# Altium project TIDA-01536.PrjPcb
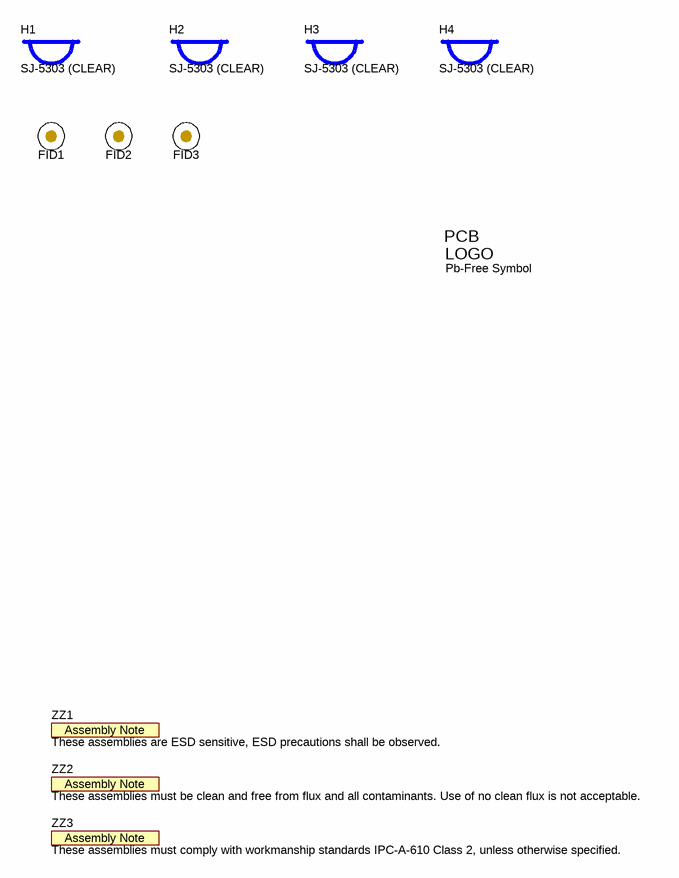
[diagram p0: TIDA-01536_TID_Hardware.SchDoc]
CopyrightYear: 2017; EVM_Orderable: N/A; PCB_Layout: CW; PCB_Rev: A; PRJ_Customer: Public Release; PRJ_Engineer: CW + KD; PRJ_Number: TIDA-01536; PRJ_Title: Single-Channel, Isolated, 3-Wire Current Loop Transmitter Reference Design; SCH_Rev: A; TechSupport: http://www.ti.com/support; TID: TIDA-01536
3 sheets, 52 parts. Net scope: global (net labels, ports and power ports of the same name join across sheets).
Board file: TIDA-01536_TID.PcbDoc
Sheets:
  TIDA-01536_TID_Hardware.SchDoc
  TIDA-01536_CoverSheet.SchDoc
  TIDA-01536_BlankSheet.SchDoc

## Sheet TIDA-01536_TID_Hardware.SchDoc
size 431 x 279 mm; Date: Not shown in title block; ApprovedBy: Not shown in title block; CheckedBy: Not shown in title block; Author: Not shown in title block; CompanyName: Not shown in title block; Engineer: Not shown in title block; Organization: Not shown in title block; Address1: Not shown in title block; Address2: Not shown in title block; Address3: Not shown in title block; Address4: Not shown in title block; DocumentNumber: 1; Revision: Use project parameter SCH_Rev; SheetNumber: 3; SheetTotal: 3; PageSetup: Record=PageOptions¦CenterHorizontal=True¦CenterVertical=True¦PrintScale=1.00¦XCorrection=1.00¦YCorrection=1.00¦PrintKind=0¦BorderSize=5000000¦LeftOffset=0¦BottomOffset=0¦Orientation=2¦PaperLength=1000¦PaperWidth=1000¦Scale=100¦PaperSource=15¦PrintQuality=600¦MediaType=1¦DitherType=10¦PaperKind=Letter¦PrintScaleMode=1

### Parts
FID1  Fiducial  [Fiducial10-20]  (value not drawn)
FID2  Fiducial  [Fiducial10-20]  (value not drawn)
FID3  Fiducial  [Fiducial10-20]  (value not drawn)
H1  SJ-5303 (CLEAR)  [Bumpon_SJ5003Transparent]
H2  SJ-5303 (CLEAR)  [Bumpon_SJ5003Transparent]
H3  SJ-5303 (CLEAR)  [Bumpon_SJ5003Transparent]
H4  SJ-5303 (CLEAR)  [Bumpon_SJ5003Transparent]
Logo2  Pb-Free Symbol  [Pb-Free_Overlay_Small]  (no BOM)
ZZ1  These assemblies are ESD sensitive, ESD precautions shall be observed.  [AssemblyNote]  (no BOM)
ZZ2  These assemblies must be clean and free from flux and all contaminants. Use of no clean flux is not acceptable.  [AssemblyNote]  (no BOM)
ZZ3  These assemblies must comply with workmanship standards IPC-A-610 Class 2, unless otherwise specified.  [AssemblyNote]  (no BOM)

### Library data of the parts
FID1-FID3 = Fiducial: Fiducial mark.  There is nothing to buy or mount.; SymbolCreator: codlsc
H1-H4 = SJ-5303 (CLEAR): Bumpon, Hemisphere, 0.44 X 0.20, Clear; Manufacturer: 3M; SymbolCreator: a0412235
Logo2 = Pb-Free: SymbolCreator: a0412235
ZZ1-ZZ3 = AssemblyNote: SymbolCreator: codlsc

## Sheet TIDA-01536_CoverSheet.SchDoc
size 431 x 279 mm; Date: Not shown in title block; ApprovedBy: Not shown in title block; CheckedBy: Not shown in title block; Author: Not shown in title block; CompanyName: Not shown in title block; Engineer: Not shown in title block; Organization: Not shown in title block; Address1: Not shown in title block; Address2: Not shown in title block; Address3: Not shown in title block; Address4: Not shown in title block; DocumentNumber: 1; Revision: Use project parameter SCH_Rev; SheetNumber: 1; SheetTotal: 3; PageSetup: Record=PageOptions¦CenterHorizontal=True¦CenterVertical=True¦PrintScale=1.00¦XCorrection=1.00¦YCorrection=1.00¦PrintKind=0¦BorderSize=5000000¦LeftOffset=0¦BottomOffset=0¦Orientation=2¦PaperLength=1000¦PaperWidth=1000¦Scale=100¦PaperSource=15¦PrintQuality=600¦MediaType=1¦DitherType=10¦PaperKind=Letter¦PrintScaleMode=1
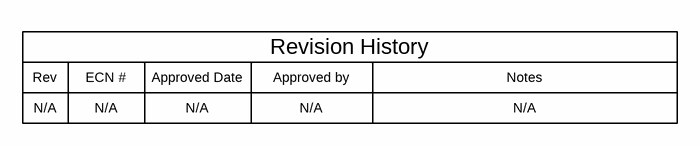
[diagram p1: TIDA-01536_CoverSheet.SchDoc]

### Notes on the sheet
- Rev
- N/A
- ECN #
- Approved Date
- Approved by
- Revision History
- Notes

## Sheet TIDA-01536_BlankSheet.SchDoc
size 431 x 279 mm; Date: Not shown in title block; ApprovedBy: Not shown in title block; CheckedBy: Not shown in title block; Author: Not shown in title block; CompanyName: Not shown in title block; DrawnBy: CW; Engineer: Not shown in title block; Organization: Not shown in title block; Address1: Not shown in title block; Address2: Not shown in title block; Address3: Not shown in title block; Address4: Not shown in title block; DocumentNumber: TIPD203; Revision: Use project parameter SCH_Rev; SheetNumber: 2; SheetTotal: 3; PageSetup: Record=PageOptions¦CenterHorizontal=True¦CenterVertical=True¦PrintScale=1.00¦XCorrection=1.00¦YCorrection=1.00¦PrintKind=0¦BorderSize=5000000¦LeftOffset=0¦BottomOffset=0¦Orientation=2¦PaperLength=1000¦PaperWidth=1000¦Scale=100¦PaperSource=15¦PrintQuality=600¦MediaType=1¦DitherType=10¦PaperKind=Letter¦PrintScaleMode=1
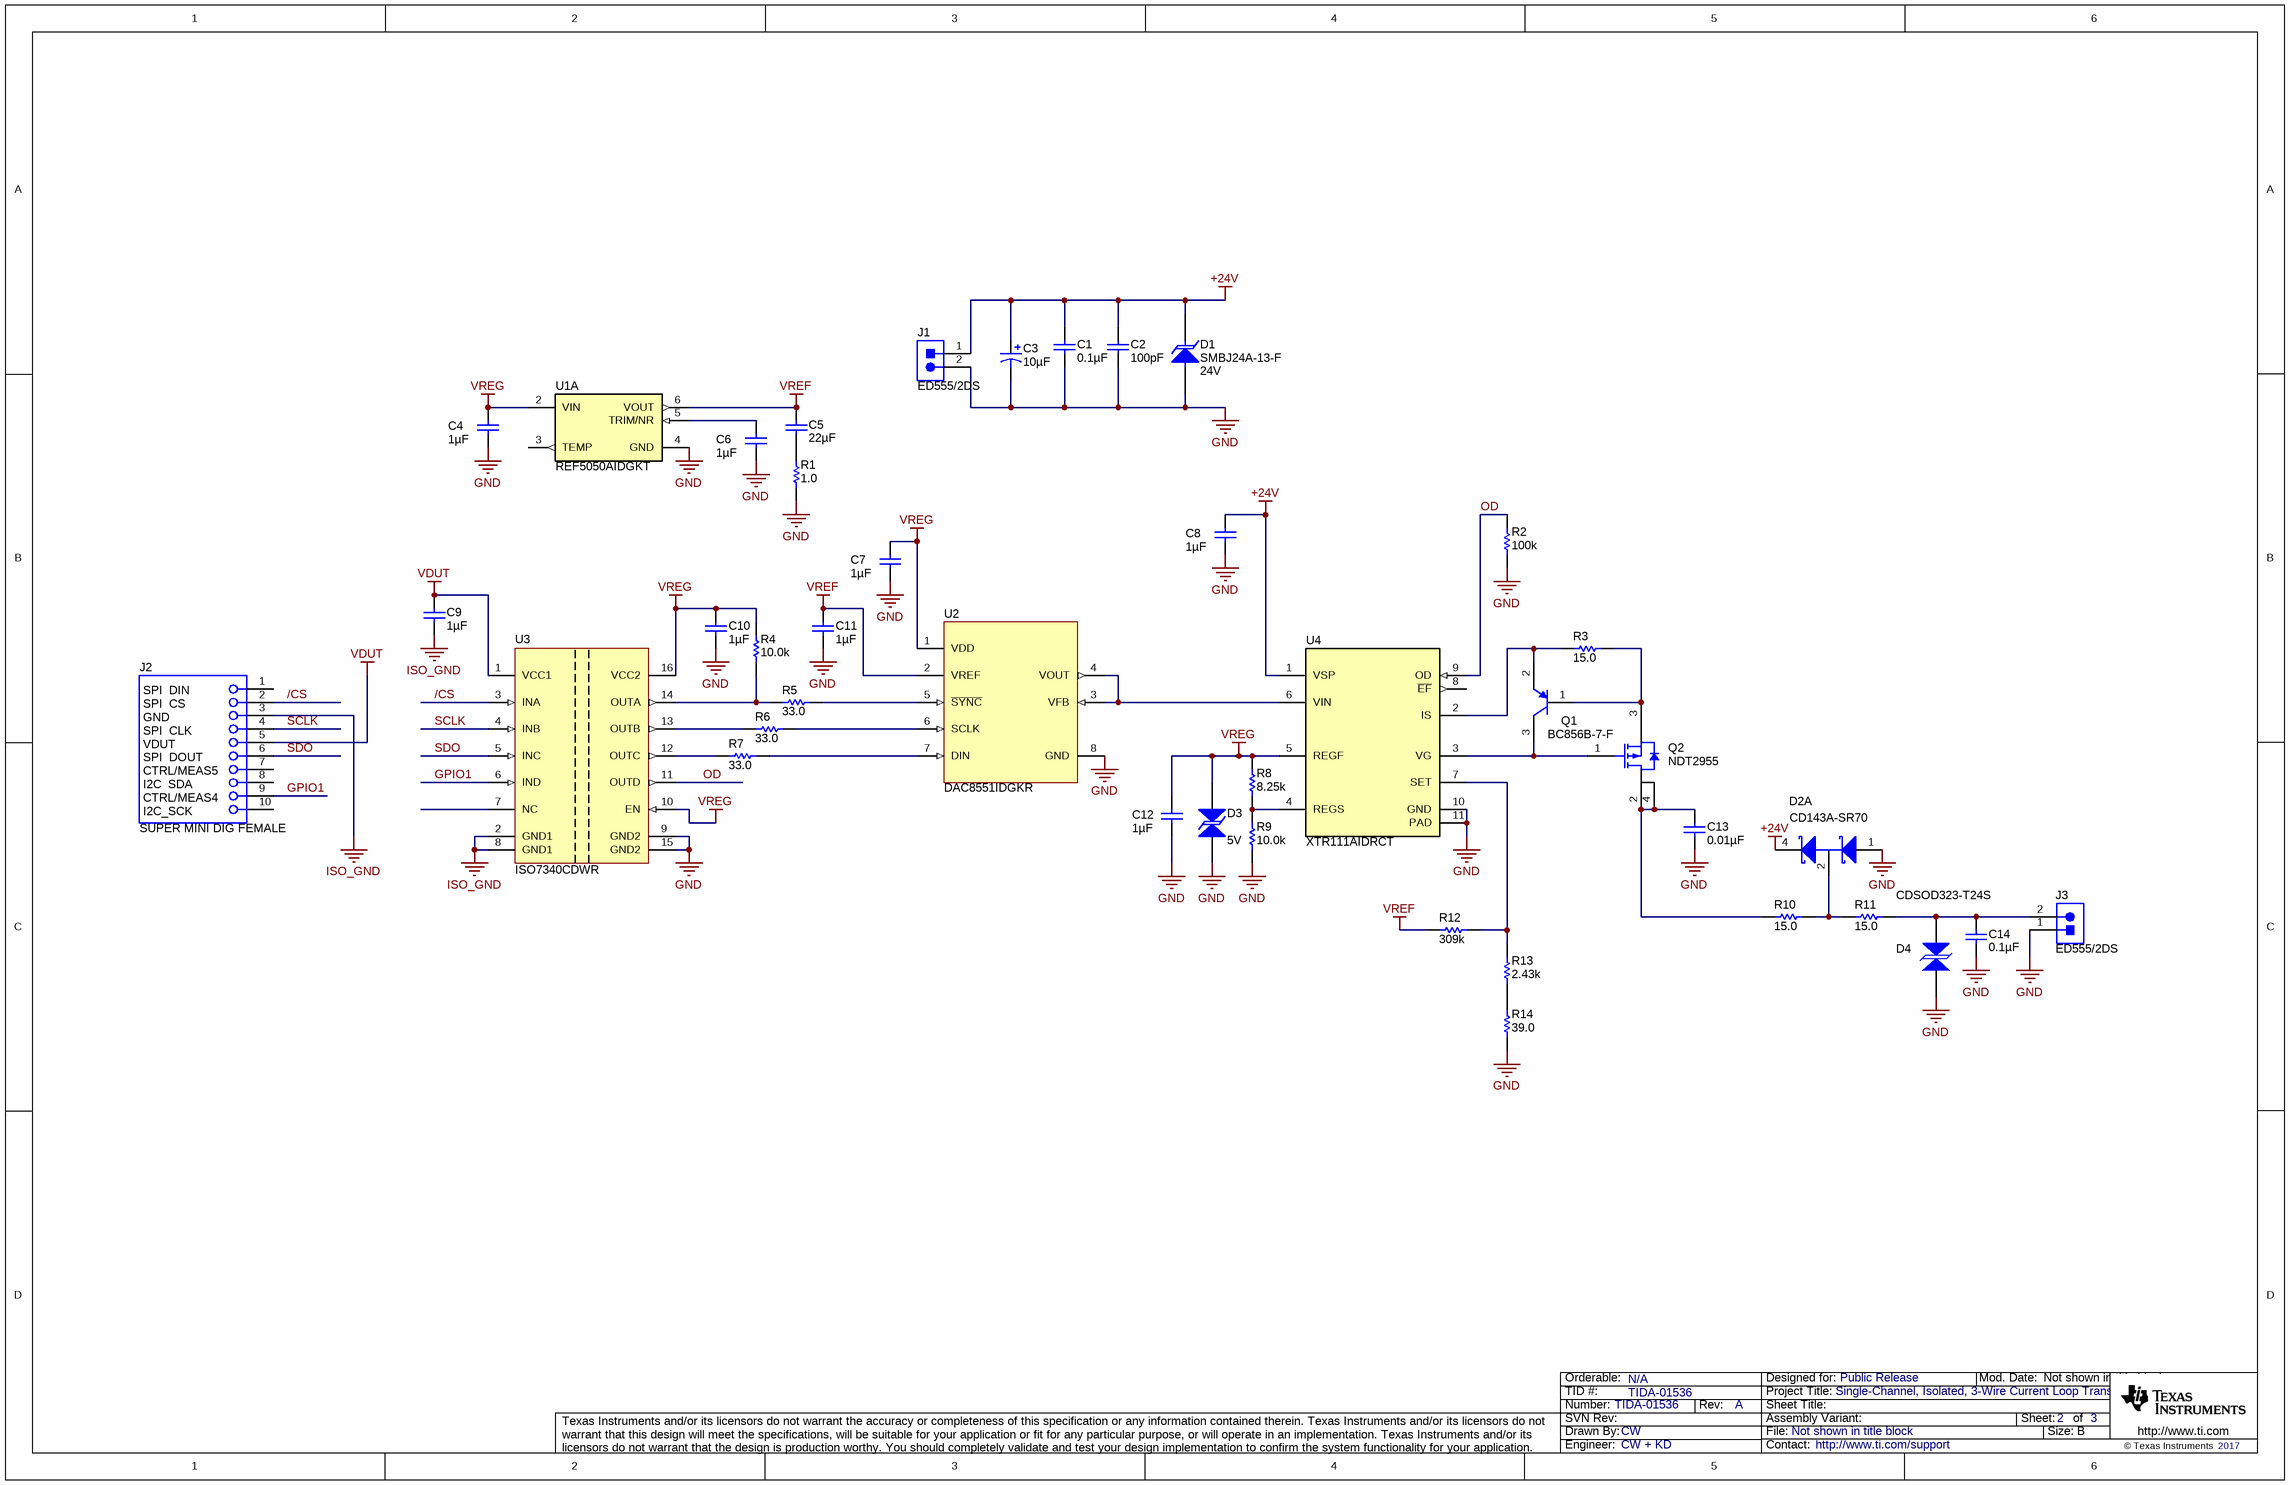
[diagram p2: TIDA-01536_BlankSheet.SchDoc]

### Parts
C1  ValueDisplayed: 0.1µF  [0603]  (hidden comment: GRM188R71H104KA93D)
C2  ValueDisplayed: 100pF  [0603]  (hidden comment: 06035A101JAT2A)
C3  ValueDisplayed: 10µF  [7343-43]  (hidden comment: 293D106X9050E2TE3)
C4  ValueDisplayed: 1µF  [0603]  (hidden comment: GRM188R71E105KA12D)
C5  ValueDisplayed: 22µF  [1206]  (hidden comment: GRM31CR61C226ME15L)
C6  ValueDisplayed: 1µF  [0603]  (hidden comment: GRM188R71E105KA12D)
C7  ValueDisplayed: 1µF  [0603]  (hidden comment: GRM188R71E105KA12D)
C8  ValueDisplayed: 1µF  [0603]  (hidden comment: GRM188R71E105KA12D)
C9  ValueDisplayed: 1µF  [0603]  (hidden comment: GRM188R71E105KA12D)
C10  ValueDisplayed: 1µF  [0603]  (hidden comment: GRM188R71E105KA12D)
C11  ValueDisplayed: 1µF  [0603]  (hidden comment: GRM188R71E105KA12D)
C12  ValueDisplayed: 1µF  [0603]  (hidden comment: GRM188R71E105KA12D)
C13  ValueDisplayed: 0.01µF  [0603]  (hidden comment: GRM188R72A103KA01D)
C14  ValueDisplayed: 0.1µF  [0603]  (hidden comment: GRM188R71H104KA93D)
D1  SMBJ24A-13-F  value 24V  [SMB]
D2  CD143A-SR70  [SOT-143-4]  (part A of 2)
D3  value 5V  [SOD-323-Bi]  (hidden comment: CDSOD323-T05)
D4  CDSOD323-T24S  [sod-323]
J1  ED555/2DS  [TERM_BLK_ED555-2DS]
J2  SUPER MINI DIG FEMALE  [CONN_851-43-010-20-001000]
J3  ED555/2DS  [TERM_BLK_ED555-2DS]
Q1  BC856B-7-F  [SOT-23]
Q2  NDT2955  [SOT-223]
R1  ValueDisplayed: 1.0  [0603]  (hidden comment: CRCW06031R00JNEA)
R2  ValueDisplayed: 100k  [0603]  (hidden comment: CRCW0603100KFKEA)
R3  ValueDisplayed: 15.0  [0603]  (hidden comment: CRCW060315R0FKEA)
R4  ValueDisplayed: 10.0k  [0603]  (hidden comment: RC0603FR-0710KL)
R5  ValueDisplayed: 33.0  [0603]  (hidden comment: CRCW060333R0FKEA)
R6  ValueDisplayed: 33.0  [0603]  (hidden comment: CRCW060333R0FKEA)
R7  ValueDisplayed: 33.0  [0603]  (hidden comment: CRCW060333R0FKEA)
R8  ValueDisplayed: 8.25k  [0603]  (hidden comment: RG1608P-8251-B-T5)
R9  ValueDisplayed: 10.0k  [0603]  (hidden comment: RG1608P-103-B-T5)
R10  ValueDisplayed: 15.0  [0805_HV]  (hidden comment: CRCW080515R0FKEA)
R11  ValueDisplayed: 15.0  [0805_HV]  (hidden comment: CRCW080515R0FKEA)
R12  ValueDisplayed: 309k  [0603]  (hidden comment: RG1608P-3093-B-T5)
R13  ValueDisplayed: 2.43k  [0603]  (hidden comment: RG1608P-2431-B-T5)
R14  ValueDisplayed: 39.0  [0603]  (hidden comment: 2-1676481-2)
U1  REF5050AIDGKT  [DGK0008A_N]  (part A of 2)
U2  DAC8551IDGKR  [DGK0008A_N]
U3  ISO7340CDWR  [DW0016B_N]
U4  XTR111AIDRCT  [DRC0010A]

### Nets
+24V: C1.2 C2.1 C3.1(+) C8.1 D1.1(K) D2.4 J1.1 U4.1(VSP)
GND: C1.1 C2.2 C3.2(-) C4.2 C6.2 C7.2 C8.2 C10.2 C11.2 C12.2 C13.2 C14.2 D1.2(A) D2.1 D3.1 D4.2 J1.2 J3.1 R1.1 R2.1 R9.2 R14.1 U1.4(GND) U2.8(GND) U3.9(GND2) U3.15(GND2) U4.10(GND) U4.11(PAD)
ISO_GND: C9.2 J2.3 U3.2(GND1) U3.8(GND1)
VDUT: C9.1 J2.5 U3.1(VCC1)
VREF: C5.1 C11.1 R12.2 U1.6(VOUT) U2.2(VREF)
VREG: C4.1 C7.1 C10.1 C12.1 D3.2 R4.2 R8.1 U1.2(VIN) U2.1(VDD) U3.10(EN) U3.16(VCC2) U4.5(REGF)
/CS: J2.2 U3.3(INA)
GPIO1: J2.9 U3.6(IND)
OD: R2.2 U3.11(OUTD) U4.9(OD)
SCLK: J2.4 U3.4(INB)
SDO: J2.6 U3.5(INC)
NetC5_2: C5.2 R1.2
NetC6_1: C6.1 U1.5(TRIM/NR)
NetC13_1: C13.1 Q2.2(D) Q2.4(D) R10.1
NetC14_1: C14.1 D4.1 J3.2 R11.2
NetD2_2: D2.2 R10.2 R11.1
NetQ1_1: Q1.1(B) Q2.3(S) R3.2
NetQ1_2: Q1.2(E) R3.1 U4.2(IS)
NetQ1_3: Q1.3(C) Q2.1(G) U4.3(VG)
NetR4_1: R4.1 R5.1 U3.14(OUTA)
NetR5_2: R5.2 U2.5(~{SYNC})
NetR6_1: R6.1 U3.13(OUTB)
NetR6_2: R6.2 U2.6(SCLK)
NetR7_1: R7.1 U3.12(OUTC)
NetR7_2: R7.2 U2.7(DIN)
NetR8_2: R8.2 R9.1 U4.4(REGS)
NetR12_1: R12.1 R13.2 U4.7(SET)
NetR13_1: R13.1 R14.2
NetU2_3: U2.3(VFB) U2.4(VOUT) U4.6(VIN)

Not connected (* = marked no-connect by the designer): J2 1 7 8 10; U1 3(TEMP); U3 7(NC); U4 8(~{EF})

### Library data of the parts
C1 C14 = GRM188R71H104KA93D: CAP, CERM, 0.1uF, 50V, +/-10%, X7R, 0603; Manufacturer: MuRata; Polarized: N; CompType: Capacitor; U/M: EA; Cap_F: 0.0000001; Tolerance_%: 10; VDC_V: 50; TaMin_C: -55; TaMax_C: 125
C2 = 06035A101JAT2A: CAP, CERM, 100pF, 50V, +/-5%, C0G/NP0, 0603; Manufacturer: AVX; Polarized: N; CompType: Capacitor; U/M: EA; Cap_F: 0.0000000001; Tolerance_%: 5; ESR_Ohm: 0.119; Value1: 0.119 ohm; VDC_V: 50; TaMin_C: -55; TaMax_C: 125
C3 = 293D106X9050E2TE3: CAP, TANT, 10uF, 50V, +/-10%, 0.8 ohm, 7343-43 SMD; Manufacturer: Vishay-Sprague; Polarized: Y; CompType: Capacitor; U/M: EA; Cap_F: 0.00001; Tolerance_%: 10; Value1: 0.8 ohm; VDC_V: 50; ESR_Ohm: 0.8; IRMS_A: 0.45; TaMin_C: -55; TaMax_C: 125; Cap_Case: E
C4 C6-C12 = GRM188R71E105KA12D: CAP, CERM, 1 µF, 25 V, +/- 10%, X7R, 0603; Manufacturer: MuRata; Polarized: N; CompType: Capacitor; Value: 1uF; U/M: EA; Cap_F: 0.000001; Tolerance_%: 10; Value1: Unknown; VDC_V: 25; Value2: 25V; TaMin_C: -55; TaMax_C: 125; AEC Category: Q200
C5 = GRM31CR61C226ME15L: CAP, CERM, 22 µF, 16 V, +/- 20%, X5R, 1206; Manufacturer: MuRata; Polarized: N; CompType: Capacitor; Value: 22uF; U/M: EA; Cap_F: 0.000022; Tolerance_%: 20; ESR_ohm: 0.006; Value1: 0.006 ohm; VDC_V: 16; Value2: 16V; TaMin_C: -55; TaMax_C: 85; AEC Category: Q200
C13 = GRM188R72A103KA01D: CAP, CERM, 0.01 µF, 100 V, +/- 10%, X7R, 0603; Manufacturer: MuRata; Polarized: N; CompType: Capacitor; Value: 0.01uF; U/M: EA; Cap_F: 0.00000001; Tolerance_%: 10; Value1: Unknown; VDC_V: 100; Value2: 100V; TaMin_C: -55; TaMax_C: 125; AEC Category: Q200
D1 = SMBJ24A-13-F: Diode, TVS, Uni, 24 V, 600 W, SMB; Manufacturer: Diodes Inc.; U/M: EA; Power_W: 5; Vr_V: 24; Value1: 5W; AEC Category: Q101
D2 = CD143A-SR70: IC TVS ARRAY 2-LINE 70V SOT-143; Manufacturer: Bourns; SymbolVersion: use current date i.e. 2008-05-20; SymbolCreator: Use LDAP id; U/M: EA, IN, or GM
D3 = CDSOD323-T05C: TVS DIODE 5VWM 9.8VC SOD323; Manufacturer: Bourns; U/M: EA; Power_W: 350; Vr_V: 5; Value1: 350W; AEC Category: Q101
D4 = SMAJ15CA: TVS DIODE 24VWM 43VC SMD; Manufacturer: Bourns; SymbolVersion: use current date i.e. 2008-05-20; SymbolCreator: Use LDAP id; U/M: EA, IN, or GM
J1 J3 = ED555/2DS: Terminal Block, 6A, 3.5mm Pitch, 2-Pos, TH; Manufacturer: On-Shore Technology; SymbolCreator: a0412235; CompType: Connector; U/M: EA
J2 = 851-43-010-20-001000: Receptacle, 50mil 10x1, R/A, TH; Manufacturer: Mill-Max; SymbolCreator: a0411947; U/M: EA
Q1 = BC856B-7-F, Diodes Inc.: Transistor, PNP, 65 V, 0.1 A, SOT-23; CompType: BJT; PNP: 1; NPN: 0; Vceo_V: 65; Vcesat1_V: 0.075; Value: 65 V; IcRated_A: 0.1; Value1: 0.1 A; HfeMax: 330; TaMin_C: -65; TaMax_C: 150; U/M: EA; AEC Category: Q101
Q2 = NDT2955: MOSFET, P-CH, -60 V, -2.5 A, SOT-223; Manufacturer: Fairchild Semiconductor; Alternate Manufacturer: None; SymbolCreator: a0799628; U/M: EA; ChType: P; Value: -60V; Value1: 0.5 ohm; Rdson45_ohm: 0.5; Value2: 11 nC; QgTyp_nC: 11; Vgs_V: 20; AEC Category: Q101
R1 = CRCW06031R00JNEA: RES, 1.0, 5%, 0.1 W, 0603; Manufacturer: Vishay-Dale; CompType: Resistor; Value: 1.0; Res_ohm: 1; Value_Code: 1R00; Tolerance_%: 5; Power_W: 0.1; Value2: 0.1W; VDC_V: 75; TempCo: 200 ppm/C; EIA_Code: E24; U/M: EA; AEC Category: Q200
R2 = CRCW0603100KFKEA: RES, 100 k, 1%, 0.1 W, 0603; Manufacturer: Vishay-Dale; CompType: Resistor; Value: 100k; Res_ohm: 100000; Tolerance_%: 1; Power_W: 0.1; Value2: 0.1W; VDC_V: 75; TempCo: 100 ppm/C; EIA_Code: E96; U/M: EA; AEC Category: Q200
R3 = CRCW060315R0FKEA: RES, 15.0, 1%, 0.1 W, 0603; Manufacturer: Vishay-Dale; CompType: Resistor; Value: 15.0; Res_ohm: 15; Value_Code: 15R0; Tolerance_%: 1; Power_W: 0.1; Value2: 0.1W; VDC_V: 75; TempCo: 100 ppm/C; EIA_Code: E96; U/M: EA; AEC Category: Q200
R4 = RC0603FR-0710KL: RES, 10.0 k, 1%, 0.1 W, 0603; Manufacturer: Yageo America; CompType: Resistor; Value: 10.0k; Res_ohm: 10000; Value_Code: 10k0; Tolerance_%: 1; Power_W: 0.1; Value2: 0.1W; VDC_V: 150; TempCo: 200 ppm/C; EIA_Code: E96; U/M: EA; AEC Category: Q200
R5-R7 = CRCW060333R0FKEA: RES, 33.0, 1%, 0.1 W, 0603; Manufacturer: Vishay-Dale; CompType: Resistor; Value: 33.0; Res_ohm: 33; Value_Code: 33R0; Tolerance_%: 1; Power_W: 0.1; Value2: 0.1W; VDC_V: 75; TempCo: 100 ppm/C; U/M: EA; AEC Category: Q200
R8 = RG1608P-8251-B-T5: RES, 8.25 k, 0.1%, 0.1 W, 0603; Manufacturer: Susumu Co Ltd; CompType: Resistor; Value: 8.25k; Res_ohm: 8250; Value_Code: 8k25; Tolerance_%: 0.1; Value2: 0.1W; VDC_V: 75; TempCo: 25 ppm/C; EIA_Code: E192; U/M: EA; AEC Category: Q200
R9 = RG1608P-103-B-T5: RES, 10.0 k, 0.1%, 0.1 W, 0603; Manufacturer: Susumu Co Ltd; CompType: Resistor; Value: 10.0k; Res_ohm: 10000; Value_Code: 10k0; Tolerance_%: 0.1; Value2: 0.1W; VDC_V: 75; TempCo: 25 ppm/C; EIA_Code: E192; U/M: EA; AEC Category: Q200
R10 R11 = CRCW080515R0FKEA: RES, 15.0, 1%, 0.125 W, 0805; Manufacturer: Vishay-Dale; CompType: Resistor; Value: 15.0; Res_ohm: 15; Value_Code: 15R0; Tolerance_%: 1; Power_W: 0.125; Value2: 0.125W; VDC_V: 150; TempCo: 100 ppm/C; EIA_Code: E96; U/M: EA; AEC Category: Q200
R12 = RG1608P-3093-B-T5: RES, 309 k, 0.1%, 0.1 W, 0603; Manufacturer: Susumu Co Ltd; CompType: Resistor; Value: 309k; Res_ohm: 309000; Tolerance_%: 0.1; Value2: 0.1W; VDC_V: 75; TempCo: 25 ppm/C; EIA_Code: E192; U/M: EA; AEC Category: Q200
R13 = RG1608P-2431-B-T5: RES, 2.43 k, 0.1%, 0.1 W, 0603; Manufacturer: Susumu Co Ltd; CompType: Resistor; Value: 2.43k; Res_ohm: 2430; Value_Code: 2k43; Tolerance_%: 0.1; Value2: 0.1W; VDC_V: 75; TempCo: 25 ppm/C; EIA_Code: E192; U/M: EA; AEC Category: Q200
R14 = RC0603FR-0739RL: RES SMD 39 OHM 0.1% 1/16W 0603; Manufacturer: TE Connectivity; CompType: Resistor; Value: 39.0; Res_ohm: 39; Value_Code: 39R0; Tolerance_%: 1; Power_W: 0.1; Value2: 0.1W; VDC_V: 150; U/M: EA; AEC Category: Q200
U1 = REF5050AIDGKT: Low Noise, Very Low Drift, Precision Voltage Reference, -40 to 125 degC, 8-pin VSSOP (DGK), Green (RoHS & no Sb/Br); Manufacturer: Texas Instruments; Alternate PartNumber: Equivalent; Initial Accuracy @ 25/deg C(%): 0.05; Iout/Iz(Max)(mA): 10; Iq(Max)(uA): 1000; Rating: Catalog; SubFamily: Series Voltage Reference; Temp Coeff(Max)(ppm/ degree C): 3; VI(Max)(V): 18; VI(Min)(V): 5.2; VO(V): 5
U2 = DAC8551IDGKR: 16-BIT, ULTRA-LOW GLITCH, VOLTAGE OUTPUT DIGITAL-TO-ANALOG CONVERTER, DGK0008A; Alternate PartNumber: DAC8551IDGKT; Manufacturer: Texas Instruments; SymbolCreator: a0411947; CompType: IC; U/M: EA
U3 = ISO7340CDWR: Robust EMC, Low Power, Quad-Channel Digital Isolators, DW0016B; Manufacturer: Texas Instruments; SymbolCreator: Altium; CompType: IC; U/M: EA
U4 = XTR111AIDRCT: Precision Voltage-to-Current Converter/Transmitter, DRC0010A; Manufacturer: Texas Instruments; SymbolCreator: Altium; CompType: IC; U/M: EA

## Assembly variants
001: not fitted FID1 FID2 FID3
